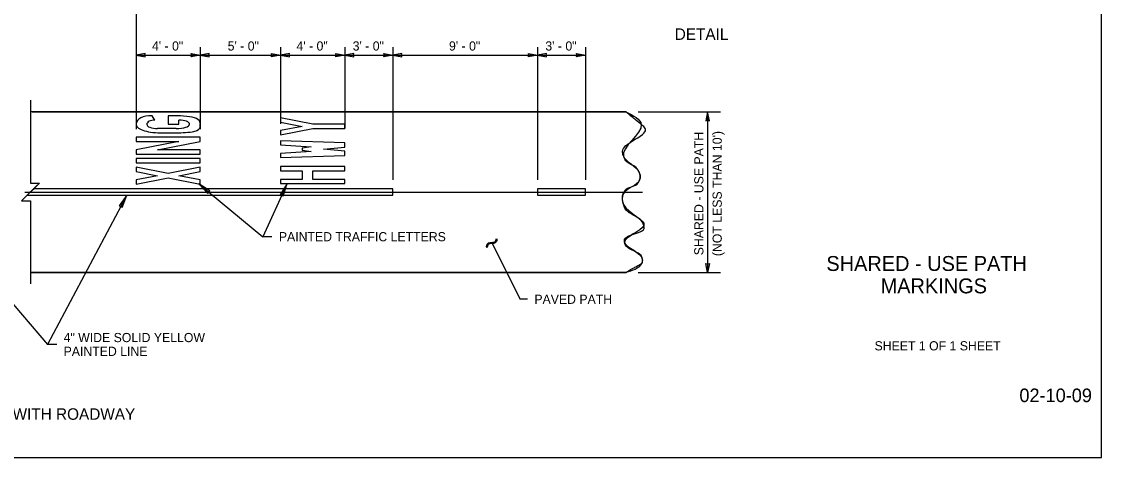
# Model space of a CAD drawing. Extents: x 99862 to 103151, y 100000 to 102076.
# Drawn here: x 101268 to 103151, y 100000 to 100759 of the extents above; entities that cross this region are included whole.
import ezdxf

# ---------------------------------------------------------------- set-up
doc = ezdxf.new("R2010")
doc.units = 0
for name, color, linetype in [('Level 1', 7, 'Continuous'), ('Level 15', 7, 'Continuous'), ('Level 2', 7, 'Continuous'), ('Level 20', 7, 'Continuous'), ('Level 8', 7, 'Continuous')]:
    doc.layers.add(name, color=color, linetype=linetype)

msp = doc.modelspace()

# ---------------------------------------------------------------- linework, layer by layer
at = {"layer": 'Level 1'}
for p, q in [((101500.2, 100587.2), (101495.5, 100594.5)), ((101532.9, 100594.6), (101523.5, 100594.6)), ((101523.5, 100594.6), (101523.5, 100579.8)), ((101542.2, 100579.8), (101542.2, 100587.2)), ((101579.5, 100579.8), (101579.5, 100581.4)), ((101467.5, 100580.7), (101467.5, 100578.8)), ((101537.5, 100572.4), (101504.9, 100572.4)), ((101514.2, 100565), (101532.8, 100565)), ((101523.5, 100579.8), (101542.2, 100579.8)), ((101579.5, 100577.8), (101579.5, 100579.8))]:
    msp.add_line(p, q, dxfattribs=at)
for points in [[(99862, 99999.5), (103151, 99999.5), (103151, 102075.5), (99862, 102075.5)], [(101504.9, 100535.1), (101579.5, 100549.9), (101579.5, 100557.3), (101467.5, 100557.3), (101467.5, 100549.9), (101542.2, 100549.9), (101467.5, 100535.1), (101467.5, 100527.7), (101579.5, 100527.7), (101579.5, 100535.1)], [(101831.5, 100525.4), (101831.5, 100532.8), (101794.2, 100536.5), (101831.5, 100540.2), (101831.5, 100547.6), (101719.5, 100551.3), (101719.5, 100543.9), (101773.1, 100540.4), (101756.9, 100538.4), (101756.9, 100534.6), (101773.1, 100532.6), (101719.5, 100529.1), (101719.5, 100521.7)], [(101579.5, 100512.9), (101579.5, 100520.3), (101467.5, 100520.3), (101467.5, 100512.9)], [(101756.9, 100498.7), (101756.9, 100483.9), (101719.5, 100483.9), (101719.5, 100476.5), (101831.5, 100476.5), (101831.5, 100483.9), (101775.5, 100483.9), (101775.5, 100498.7), (101831.5, 100498.7), (101831.5, 100506.1), (101719.5, 100506.1), (101719.5, 100498.7)], [(101523.5, 100486.6), (101579.5, 100475.5), (101579.5, 100482.9), (101542.2, 100490.3), (101579.5, 100497.7), (101579.5, 100505.1), (101523.5, 100494), (101467.5, 100505.1), (101467.5, 100497.7), (101504.9, 100490.3), (101467.5, 100482.9), (101467.5, 100475.5)]]:
    msp.add_lwpolyline(points, close=True, dxfattribs=at)
for points in [[(101500.2, 100587.2), (101495.5, 100594.5)], [(101532.9, 100594.6), (101523.5, 100594.6), (101523.5, 100579.8), (101542.2, 100579.8), (101542.2, 100587.2)], [(101579.5, 100577.8), (101579.5, 100579.8), (101579.5, 100581.4)], [(101719.5, 100584.2), (101719.5, 100583.6), (101756.9, 100576.2), (101719.5, 100568.8), (101719.5, 100561.3), (101775.5, 100572.5), (101831.5, 100572.5), (101831.5, 100579.9), (101775.5, 100579.9), (101719.5, 100591), (101719.5, 100584.2)], [(101719.5, 100584.2), (101719.5, 100583.6), (101756.9, 100576.2), (101719.5, 100568.8), (101719.5, 100561.3), (101775.5, 100572.5), (101831.5, 100572.5), (101831.5, 100579.9), (101775.5, 100579.9), (101719.5, 100591), (101719.5, 100584.2)], [(101467.5, 100580.7), (101467.5, 100578.8)], [(101537.5, 100572.4), (101504.9, 100572.4)], [(101514.2, 100565), (101532.8, 100565)], [(101579.5, 100535.1), (101504.9, 100535.1), (101579.5, 100549.9), (101579.5, 100557.3), (101467.5, 100557.3), (101467.5, 100549.9), (101542.2, 100549.9), (101467.5, 100535.1), (101467.5, 100527.7), (101579.5, 100527.7), (101579.5, 100535.1)], [(101719.5, 100521.7), (101831.5, 100525.4), (101831.5, 100532.8), (101794.2, 100536.5), (101831.5, 100540.2), (101831.5, 100547.6), (101719.5, 100551.3), (101719.5, 100543.9), (101773.1, 100540.4), (101756.9, 100538.4), (101756.9, 100534.6), (101773.1, 100532.6), (101719.5, 100529.1), (101719.5, 100521.7)], [(101467.5, 100512.9), (101579.5, 100512.9), (101579.5, 100520.3), (101467.5, 100520.3), (101467.5, 100512.9)], [(101719.5, 100498.7), (101756.9, 100498.7), (101756.9, 100483.9), (101719.5, 100483.9), (101719.5, 100476.5), (101831.5, 100476.5), (101831.5, 100483.9), (101775.5, 100483.9), (101775.5, 100498.7), (101831.5, 100498.7), (101831.5, 100506.1), (101719.5, 100506.1), (101719.5, 100498.7)], [(101467.5, 100475.5), (101523.5, 100486.6), (101579.5, 100475.5), (101579.5, 100482.9), (101542.2, 100490.3), (101579.5, 100497.7), (101579.5, 100505.1), (101523.5, 100494), (101467.5, 100505.1), (101467.5, 100497.7), (101504.9, 100490.3), (101467.5, 100482.9), (101467.5, 100475.5)]]:
    msp.add_lwpolyline(points, dxfattribs=at)
for centre, major_axis, ratio, start_param, end_param in [((101495.4, 100579.8), (27.8, -1.2), 0.530457, 1.588441, 3.159237), ((101495.4, 100579.8), (27.8, -1.2), 0.530457, 1.588441, 3.159237), ((101500.2, 100579.8), (14, 0), 0.527138, 1.570796, 3.141593), ((101500.2, 100579.8), (14, 0), 0.527138, 1.570796, 3.141593), ((101533.6, 100582.6), (46.3, 1.1), 0.258587, 0.551028, 1.580024), ((101533.6, 100582.6), (46.3, 1.1), 0.258587, 0.551028, 1.580024), ((101542.2, 100579.8), (18.7, 0), 0.396059, 6.283185, 7.853982), ((101542.2, 100579.8), (18.7, 0), 0.396059, 6.283185, 7.853982), ((101399.9, 100464.4), (177.9, 121.4), 0.218234, 6.18471, 6.411642), ((101399.9, 100464.4), (177.9, 121.4), 0.218234, 6.18471, 6.411642), ((101512.3, 100580), (44.8, 0.7), 0.335619, 3.177997, 4.748794), ((101512.3, 100580), (44.8, 0.7), 0.335619, 3.177997, 4.748794), ((101504.9, 100579.8), (18.7, 0), 0.395354, 3.141593, 4.712389), ((101504.9, 100579.8), (18.7, 0), 0.395354, 3.141593, 4.712389), ((101510.7, 100603.9), (110.2, -9.3), 0.342882, 4.943908, 5.262049), ((101510.7, 100603.9), (110.2, -9.3), 0.342882, 4.943908, 5.262049), ((101537.5, 100579.8), (23.3, 0), 0.316283, 4.712389, 6.283185), ((101537.5, 100579.8), (23.3, 0), 0.316283, 4.712389, 6.283185), ((101551.5, 100575.5), (25.1, -3), 0.341545, 5.346266, 5.838131), ((101551.5, 100575.5), (25.1, -3), 0.341545, 5.346266, 5.838131), ((101522.7, 100595.2), (56.3, -20.7), 0.362293, 5.957971, 6.431019), ((101522.7, 100595.2), (56.3, -20.7), 0.362293, 5.957971, 6.431019)]:
    msp.add_ellipse(centre, major_axis=major_axis, ratio=ratio, start_param=start_param, end_param=end_param, dxfattribs=at)
at = {"layer": 'Level 15'}
for p, q in [((101467.5, 100802), (101467.5, 100571.2)), ((101579.5, 100714.1), (101579.5, 100571.2)), ((101719.5, 100714.1), (101719.5, 100580.5)), ((101831.5, 100714.1), (101831.5, 100572.4)), ((101915.5, 100714.1), (101915.5, 100483)), ((102167.5, 100714.1), (102167.5, 100483)), ((102251.5, 100714.1), (102251.5, 100483)), ((101467.5, 100700.3), (101579.5, 100700.3)), ((101467.5, 100700.3), (101467.5, 100575.8)), ((101579.5, 100700.3), (101719.5, 100700.3)), ((101719.5, 100700.3), (101831.5, 100700.3)), ((101831.5, 100700.3), (101915.5, 100700.3)), ((101915.5, 100700.3), (102167.5, 100700.3)), ((102167.5, 100700.3), (102251.5, 100700.3)), ((102343.2, 100601.8), (102486.6, 100601.8)), ((102464.2, 100601.8), (102464.2, 100321.8)), ((101576.8, 100476), (101688.5, 100384)), ((101730.7, 100476.5), (101688.5, 100384)), ((101089.5, 100457.2), (101313.1, 100196.3)), ((101273.7, 100461.8), (102350.8, 100461.8)), ((101451.5, 100456.6), (101313.1, 100196.3)), ((101704.5, 100384), (101688.5, 100384)), ((102082.1, 100373.2), (102084.7, 100374.1)), ((102084.7, 100374.1), (102089.1, 100374.5)), ((102089.1, 100374.5), (102091.5, 100374.7)), ((102091.5, 100374.7), (102092.9, 100375.3)), ((102092.9, 100375.3), (102094, 100376.2)), ((102094.9, 100374.2), (102093.6, 100373.2)), ((102094, 100376.2), (102094.8, 100377.6)), ((102094.8, 100377.6), (102095.8, 100381.1)), ((102095.9, 100375.5), (102094.9, 100374.2)), ((102095.8, 100381.1), (102096.9, 100379.3)), ((102096.5, 100377.2), (102095.9, 100375.5)), ((102096.9, 100379.3), (102096.5, 100377.2)), ((102078.8, 100367.1), (102079.1, 100369.1)), ((102079.9, 100365.3), (102078.8, 100367.1)), ((102079.1, 100369.1), (102079.7, 100370.8)), ((102079.7, 100370.8), (102080.7, 100372.1)), ((102080.4, 100367.7), (102079.9, 100365.3)), ((102081, 100369.3), (102080.4, 100367.7)), ((102080.7, 100372.1), (102082.1, 100373.2)), ((102081.8, 100370.4), (102081, 100369.3)), ((102082.9, 100371.2), (102081.8, 100370.4)), ((102084.7, 100371.8), (102082.9, 100371.2)), ((102087.2, 100372.1), (102084.7, 100371.8)), ((102091.3, 100372.3), (102087.2, 100372.1)), ((102087.8, 100373.2), (102137.3, 100275)), ((102093.6, 100373.2), (102091.3, 100372.3)), ((102343.2, 100321.8), (102486.6, 100321.8)), ((102150.1, 100275), (102137.3, 100275)), ((101329.1, 100196.3), (101313.1, 100196.3))]:
    msp.add_line(p, q, dxfattribs=at)
for points in [[(101467.5, 100700.3), (101483.2, 100697.2), (101482.5, 100700.3), (101483.2, 100703.4)], [(101579.5, 100700.3), (101563.8, 100697.2), (101564.5, 100700.3), (101563.8, 100703.4)], [(101579.5, 100700.3), (101595.2, 100697.2), (101594.5, 100700.3), (101595.2, 100703.4)], [(101719.5, 100700.3), (101703.8, 100697.2), (101704.5, 100700.3), (101703.8, 100703.4)], [(101719.5, 100700.3), (101735.2, 100697.2), (101734.5, 100700.3), (101735.2, 100703.4)], [(101831.5, 100700.3), (101815.8, 100697.2), (101816.5, 100700.3), (101815.8, 100703.4)], [(101831.5, 100700.3), (101847.2, 100697.2), (101846.5, 100700.3), (101847.2, 100703.4)], [(101915.5, 100700.3), (101899.8, 100697.2), (101900.5, 100700.3), (101899.8, 100703.4)], [(101915.5, 100700.3), (101931.2, 100697.2), (101930.5, 100700.3), (101931.2, 100703.4)], [(102167.5, 100700.3), (102151.8, 100697.2), (102152.5, 100700.3), (102151.8, 100703.4)], [(102167.5, 100700.3), (102183.2, 100697.2), (102182.5, 100700.3), (102183.2, 100703.4)], [(102251.5, 100700.3), (102235.8, 100697.2), (102236.5, 100700.3), (102235.8, 100703.4)], [(102464.2, 100601.8), (102461.1, 100586.1), (102464.2, 100586.8), (102467.3, 100586.1)], [(101576.8, 100476), (101592.5, 100459.2), (101593.6, 100462.1), (101596.3, 100463.8)], [(101730.7, 100476.5), (101718.5, 100457), (101721.6, 100456.7), (101723.9, 100454.5)], [(101451.5, 100456.6), (101438.2, 100437.8), (101441.3, 100437.4), (101443.4, 100435)], [(102464.2, 100321.8), (102461.1, 100337.5), (102464.2, 100336.8), (102467.3, 100337.5)]]:
    msp.add_lwpolyline(points, close=True, dxfattribs=at)
msp.add_lwpolyline([(101283.3, 100621.8), (101283.3, 100477.3), (101298.8, 100477.3), (101267.8, 100446.4), (101283.3, 100446.4), (101283.3, 100301.8)], dxfattribs=at)
at = {"layer": 'Level 2'}
for p, q in [((102321.4, 100601.8), (101283.2, 100601.8)), ((101283.2, 100601.8), (101283.3, 100477.3)), ((101286, 100601.8), (102321.4, 100601.8)), ((102321.4, 100321.8), (101283.4, 100321.8))]:
    msp.add_line(p, q, dxfattribs=at)
for points in [[(101292.3, 100471.1), (101288.5, 100467.2), (101267.8, 100446.4)], [(101283.3, 100477.3), (101298.8, 100477.3), (101292.3, 100471.1)], [(101267.8, 100446.4), (101283.3, 100446.4), (101283.4, 100321.8), (102321.4, 100321.8)]]:
    msp.add_lwpolyline(points, dxfattribs=at)
msp.add_spline([(102321.4, 100601.8), (102348.5, 100579.5), (102317.6, 100524.4), (102345.6, 100494.4), (102345.6, 100482.8), (102317.6, 100459.5), (102317.6, 100440.2), (102352.9, 100403.4), (102319.5, 100374.4), (102350.5, 100342.9), (102349, 100337.2), (102321.4, 100321.8)], degree=3, dxfattribs=at)
msp.add_open_spline([(102321.4, 100321.8), (102330.6, 100326.9), (102339.8, 100332.1), (102349, 100337.2), (102350.7, 100338.2), (102350.5, 100341.5), (102350.5, 100342.9), (102349.9, 100353.8), (102321.3, 100364.6), (102319.5, 100374.4), (102317.6, 100384.2), (102356.2, 100393.6), (102352.9, 100403.4), (102349, 100414.8), (102321.6, 100427.2), (102317.6, 100440.2), (102316, 100445.1), (102315.2, 100454.1), (102317.6, 100459.5), (102322, 100469.8), (102341.2, 100472.5), (102345.6, 100482.8), (102347, 100486), (102346.7, 100491.3), (102345.6, 100494.4), (102341.9, 100505.4), (102321.3, 100513.4), (102317.6, 100524.4), (102311.8, 100541.4), (102364.8, 100566.2), (102348.5, 100579.5), (102339.5, 100587), (102330.5, 100594.4), (102321.4, 100601.8)], degree=3, dxfattribs=at)
at = {"layer": 'Level 8'}
msp.add_line((101289.5, 100467.2), (101281.5, 100460.4), dxfattribs=at)
for points in [[(101277.5, 100456.4), (101915.5, 100456.4), (101915.5, 100467.2), (101289.5, 100467.2)], [(101281.5, 100460.4), (101277.5, 100456.4)]]:
    msp.add_lwpolyline(points, dxfattribs=at)
msp.add_lwpolyline([(102167.5, 100456.4), (102251.5, 100456.4), (102251.5, 100467.2), (102167.5, 100467.2)], close=True, dxfattribs=at)

# ---------------------------------------------------------------- texts
at = {"layer": 'Level 1'}
msp.add_text('02-10-09', height=23.62, dxfattribs=at).set_placement((103008, 100095.8))
at = {"layer": 'Level 20'}
for s, height, p in [('DETAIL', 20, (102406.9, 100726.9)), ('4\' - 0"', 16, (101495.2, 100708.3)), ('5\' - 0"', 16, (101627.2, 100708.3)), ('4\' - 0"', 16, (101747.2, 100708.3)), ('3\' - 0"', 16, (101845.2, 100708.3)), ('9\' - 0"', 16, (102013.2, 100708.3)), ('3\' - 0"', 16, (102181.2, 100708.3)), ('SHARED - USE PATH', 26, (102671.4, 100324.3)), (' MARKINGS', 26, (102756.3, 100285.3)), ('SHEET 1 OF 1 SHEET', 16, (102755.4, 100185.9)), ('MARKING AT INTERSECTION WITH ROADWAY', 20, (100871.7, 100065))]:
    msp.add_text(s, height=height, dxfattribs=at).set_placement(p)
for s, rotation, p in [('SHARED - USE PATH', 90, (102456.9, 100351.6)), ("(NOT LESS THAN 10')", 90, (102488.9, 100350.1)), ('PAINTED TRAFFIC LETTERS', 360, (101716.5, 100376)), ('PAVED PATH', 360, (102162.1, 100267)), ('4" WIDE SOLID YELLOW ', 360, (101341.1, 100200.3)), ('PAINTED LINE', 360, (101341.1, 100176.3))]:
    msp.add_text(s, height=16, rotation=rotation, dxfattribs=at).set_placement(p)

doc.saveas('drawing.dxf')
